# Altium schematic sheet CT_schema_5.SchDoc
size 454 x 431 mm
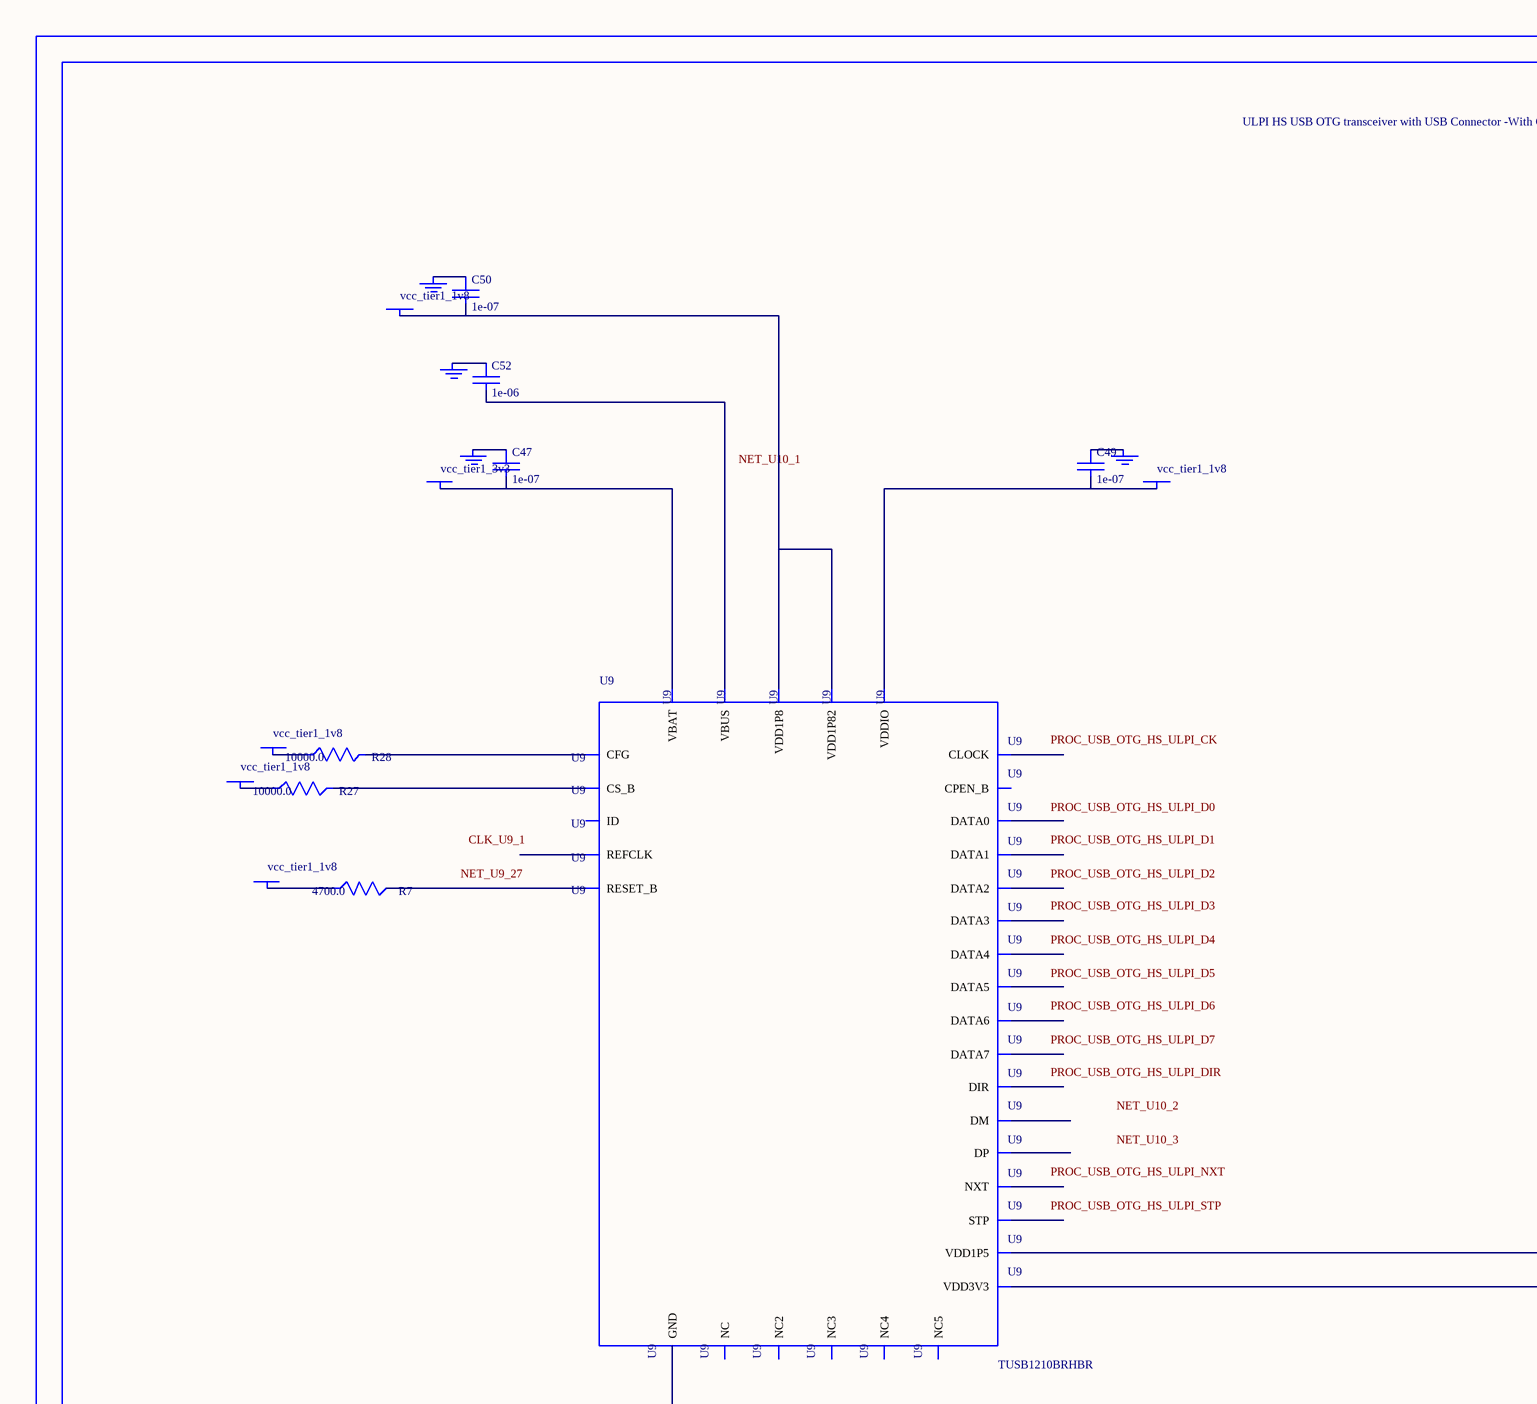
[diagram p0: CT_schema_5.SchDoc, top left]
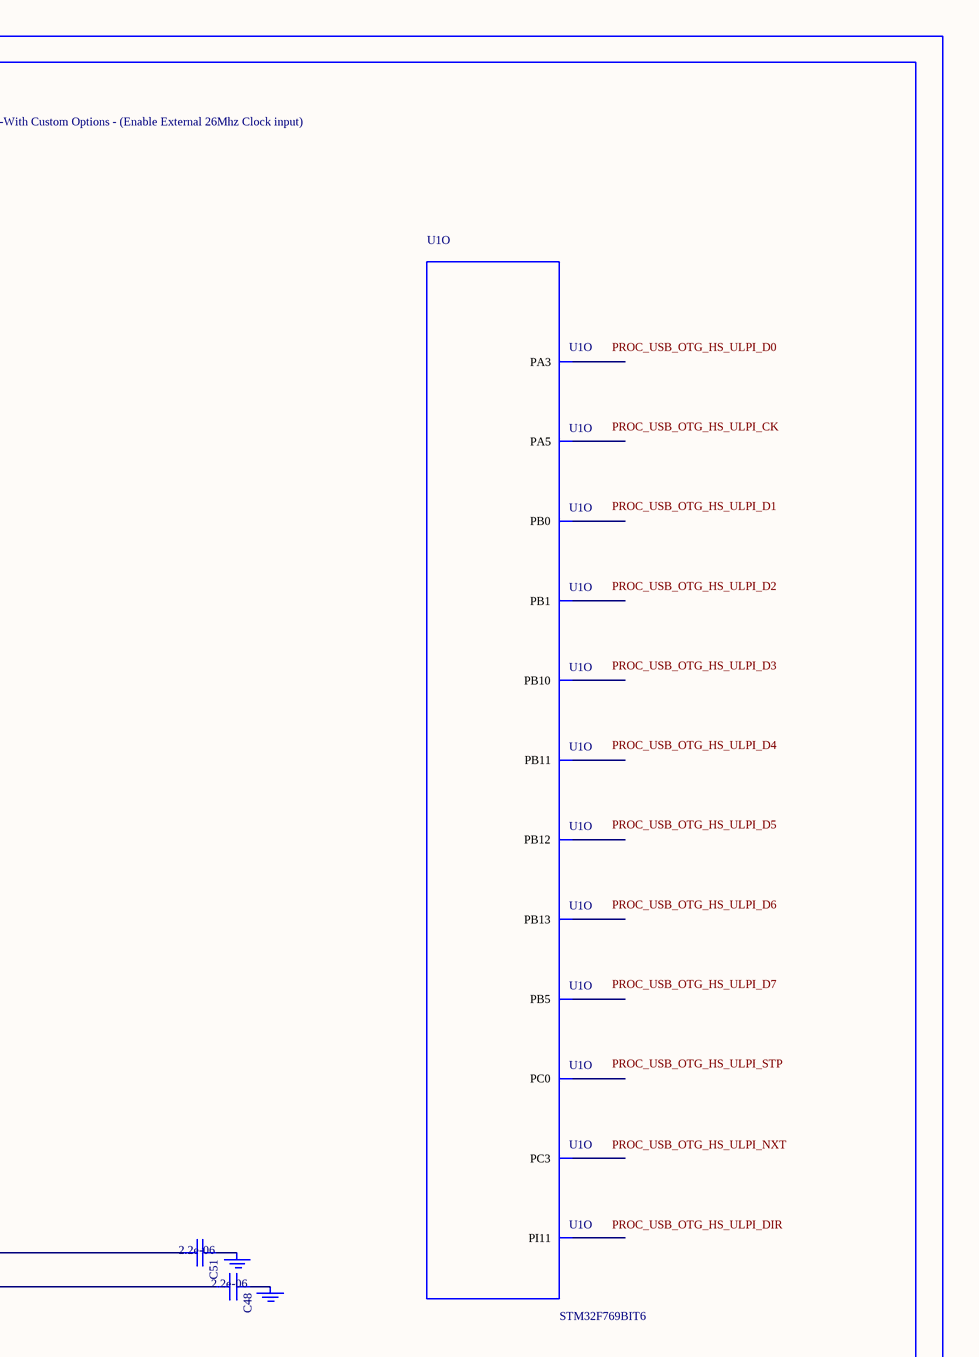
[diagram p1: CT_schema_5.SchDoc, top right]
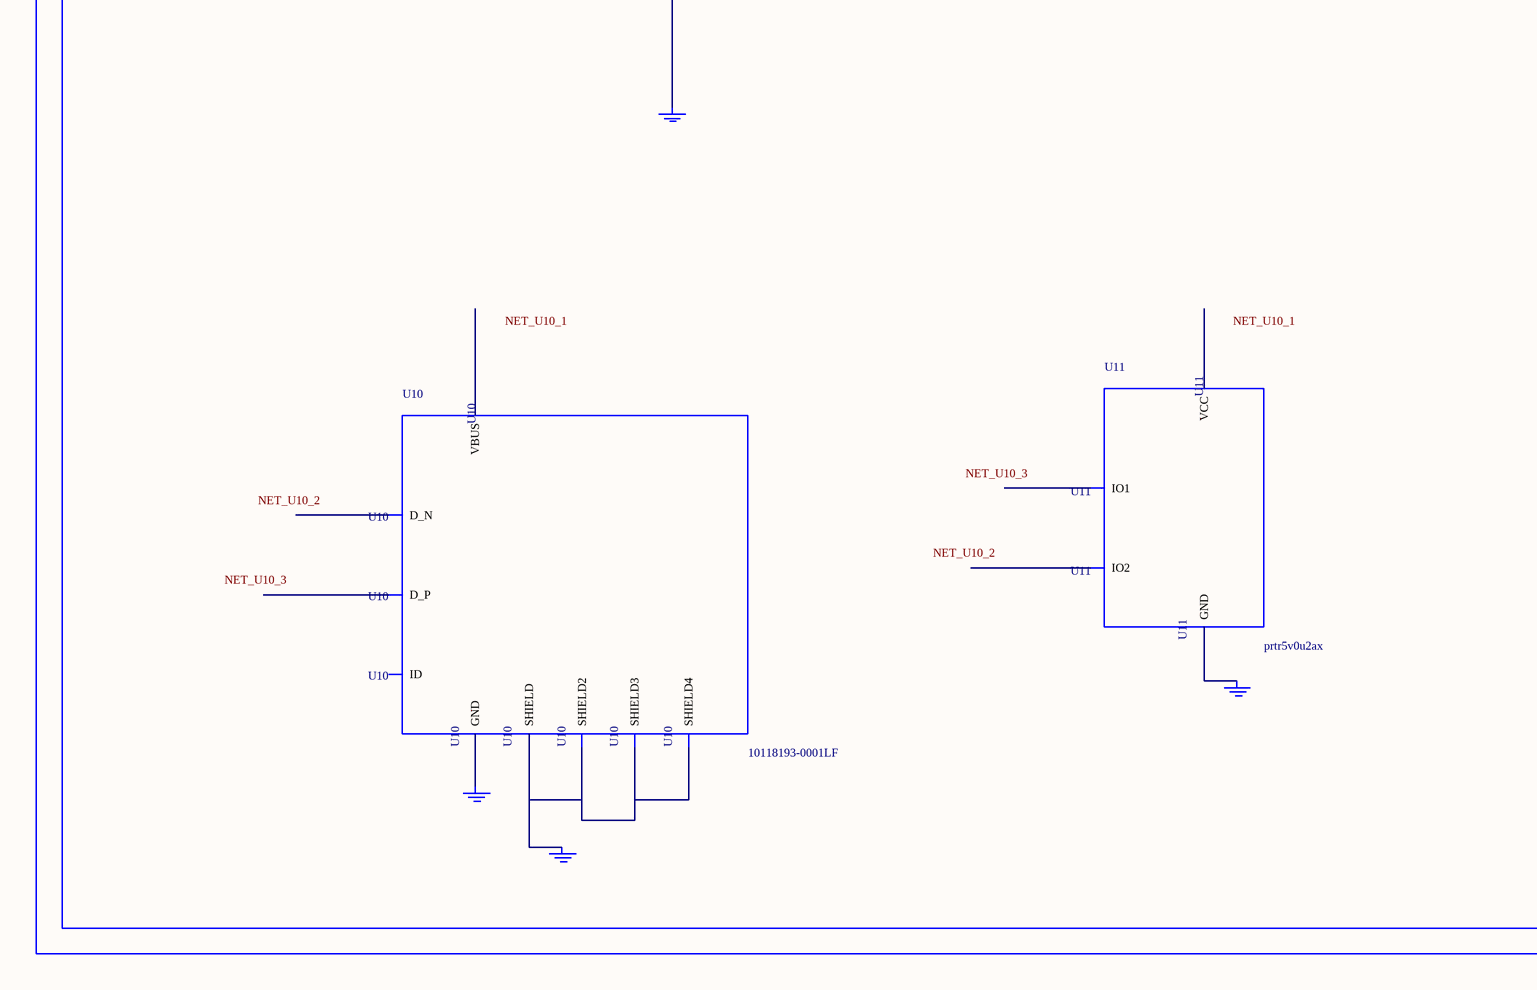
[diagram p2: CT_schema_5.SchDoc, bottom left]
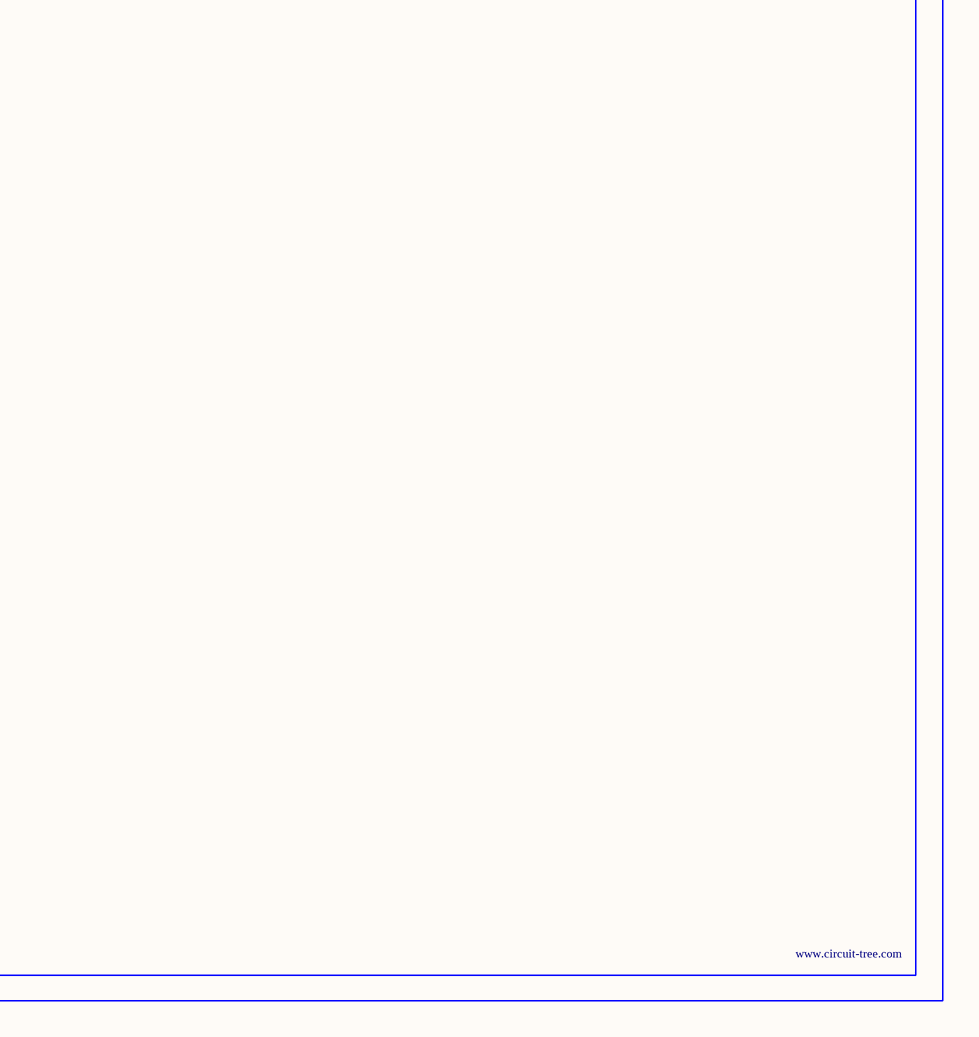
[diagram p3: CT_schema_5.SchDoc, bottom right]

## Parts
BORDER4  (no value)
C47  1e-07  [C0402]
C48  2.2e-06  [C0603]
C49  1e-07  [C0402]
C50  1e-07  [C0402]
C51  2.2e-06  [C0603]
C52  1e-06  [C0603]
GND_INSTANCE_4_0  (no value)
GND_INSTANCE_4_1  (no value)
GND_INSTANCE_4_2  (no value)
GND_INSTANCE_4_3  (no value)
GND_INSTANCE_4_4  (no value)
GND_INSTANCE_4_5  (no value)
GND_INSTANCE_4_6  (no value)
GND_INSTANCE_4_7  (no value)
GND_INSTANCE_4_8  (no value)
GND_INSTANCE_4_9  (no value)
POWER_INSTANCE_4_0  vcc_tier1_1v8
POWER_INSTANCE_4_1  vcc_tier1_1v8
POWER_INSTANCE_4_2  vcc_tier1_3v3
POWER_INSTANCE_4_3  vcc_tier1_1v8
POWER_INSTANCE_4_4  vcc_tier1_1v8
POWER_INSTANCE_4_5  vcc_tier1_1v8
R7  4700.0  [R0603]
R27  10000.0  [R0603]
R28  10000.0  [R0603]
U1  STM32F769BIT6  [LQFP208]  (part O of 15)
U9  TUSB1210BRHBR  [RHB32_3P45X3P45]
U10  10118193-0001LF  [FCI_10118193-0001LF]
U11  prtr5v0u2ax  [SOT143B]

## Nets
NetC47_1: C47.1 GND_INSTANCE_4_2.0(GND)
NetC47_2: C47.2 POWER_INSTANCE_4_2.0(PWR) U9.21(VBAT)
NetC48_1: C48.1 GND_INSTANCE_4_1.0(GND)
NetC48_2: C48.2 U9.20(VDD3V3)
NetC49_1: C49.1 GND_INSTANCE_4_5.0(GND)
NetC49_2: C49.2 POWER_INSTANCE_4_4.0(PWR) U9.32(VDDIO)
NetC50_1: C50.1 GND_INSTANCE_4_4.0(GND)
NetC50_2: C50.2 POWER_INSTANCE_4_3.0(PWR) U9.28(VDD1P8) U9.30(VDD1P82)
NetC51_1: C51.1 GND_INSTANCE_4_0.0(GND)
NetC51_2: C51.2 U9.12(VDD1P5)
NetC52_1: C52.1 GND_INSTANCE_4_3.0(GND)
NetC52_2: C52.2 U9.22(VBUS)
NetGND_INSTANCE_4_6_0: GND_INSTANCE_4_6.0(GND) U9.33(GND)
NetGND_INSTANCE_4_7_0: GND_INSTANCE_4_7.0(GND) U10.6(SHIELD) U10.7(SHIELD2) U10.8(SHIELD3) U10.9(SHIELD4)
NetGND_INSTANCE_4_8_0: GND_INSTANCE_4_8.0(GND) U10.5(GND)
NetGND_INSTANCE_4_9_0: GND_INSTANCE_4_9.0(GND) U11.1(GND)
NetPOWER_INSTANCE_4_0_0: POWER_INSTANCE_4_0.0(PWR) R27.1
NetPOWER_INSTANCE_4_1_0: POWER_INSTANCE_4_1.0(PWR) R28.1
NetPOWER_INSTANCE_4_5_0: POWER_INSTANCE_4_5.0(PWR) R7.1
NetR7_2: R7.2 U9.27(RESET_B)
NetR27_2: R27.2 U9.11(CS_B)
NetR28_2: R28.2 U9.14(CFG)

Not connected (* = marked no-connect by the designer): U1 13(PI11) 35(PC0) 38(PC3) 50(PA3) 54(PA5) 61(PB0) 62(PB1) 90(PB10) 91(PB11) 104(PB12) 105(PB13) 194(PB5); U9 1(REFCLK) 2(NXT) 3(DATA0) 4(DATA1) 5(DATA2) 6(DATA3) 7(DATA4) 8(NC) 9(DATA5) 10(DATA6) 13(DATA7) 15(NC2) 16(NC3) 17(CPEN_B) 18(DP) 19(DM) 23(ID) 24(NC4) 25(NC5) 26(CLOCK) 29(STP) 31(DIR); U10 1(VBUS) 2(D_N) 3(D_P) 4(ID); U11 2(IO1) 3(IO2) 4(VCC)

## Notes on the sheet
- Labels drawn without touching a wire or pin: CLK_U9_1, NET_U9_27, NET_U10_1, NET_U10_2, NET_U10_3, PROC_USB_OTG_HS_ULPI_CK, PROC_USB_OTG_HS_ULPI_D0, PROC_USB_OTG_HS_ULPI_D1, PROC_USB_OTG_HS_ULPI_D2, PROC_USB_OTG_HS_ULPI_D3, PROC_USB_OTG_HS_ULPI_D4, PROC_USB_OTG_HS_ULPI_D5, PROC_USB_OTG_HS_ULPI_D6, PROC_USB_OTG_HS_ULPI_D7, PROC_USB_OTG_HS_ULPI_DIR, PROC_USB_OTG_HS_ULPI_NXT, PROC_USB_OTG_HS_ULPI_STP

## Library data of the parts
BORDER4 = BORDER_PAGE4
C47 C49 C50 = C0402C104K3RACTU
C48 C51 = C0603C225K8RACTU
C52 = C0603C105K3RACTU
GND_INSTANCE_4_0-GND_INSTANCE_4_9 = GND
POWER_INSTANCE_4_0-POWER_INSTANCE_4_5 = PWR
R7 = RC0603JR-074K7L
R27 R28 = RC0603JR-0710KL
